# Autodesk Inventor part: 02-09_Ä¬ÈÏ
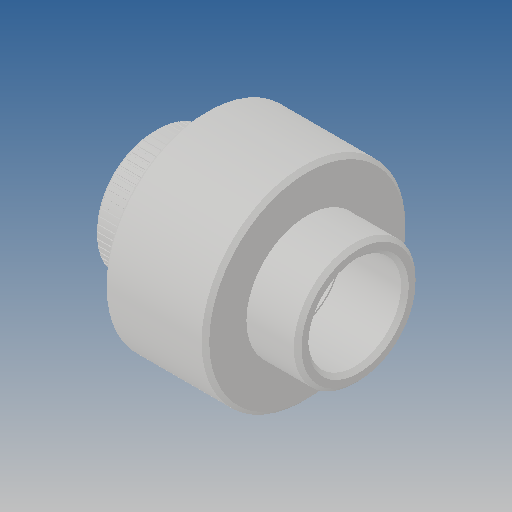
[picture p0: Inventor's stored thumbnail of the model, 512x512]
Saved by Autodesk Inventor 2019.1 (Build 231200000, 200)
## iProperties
Created: 2010-06
Part Number: 02-09_Ä¬ÈÏ
Material: Ogólny
Document SubType Name: Modeling
Designer: CADENGINEERING4
Density: 1 g/cm^3
Appearance: Domyślna
Author: CADENGINEERING4
Revision Number: ÈÎºÎ
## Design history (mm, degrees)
feature "NONE"
node "Bryła1"
